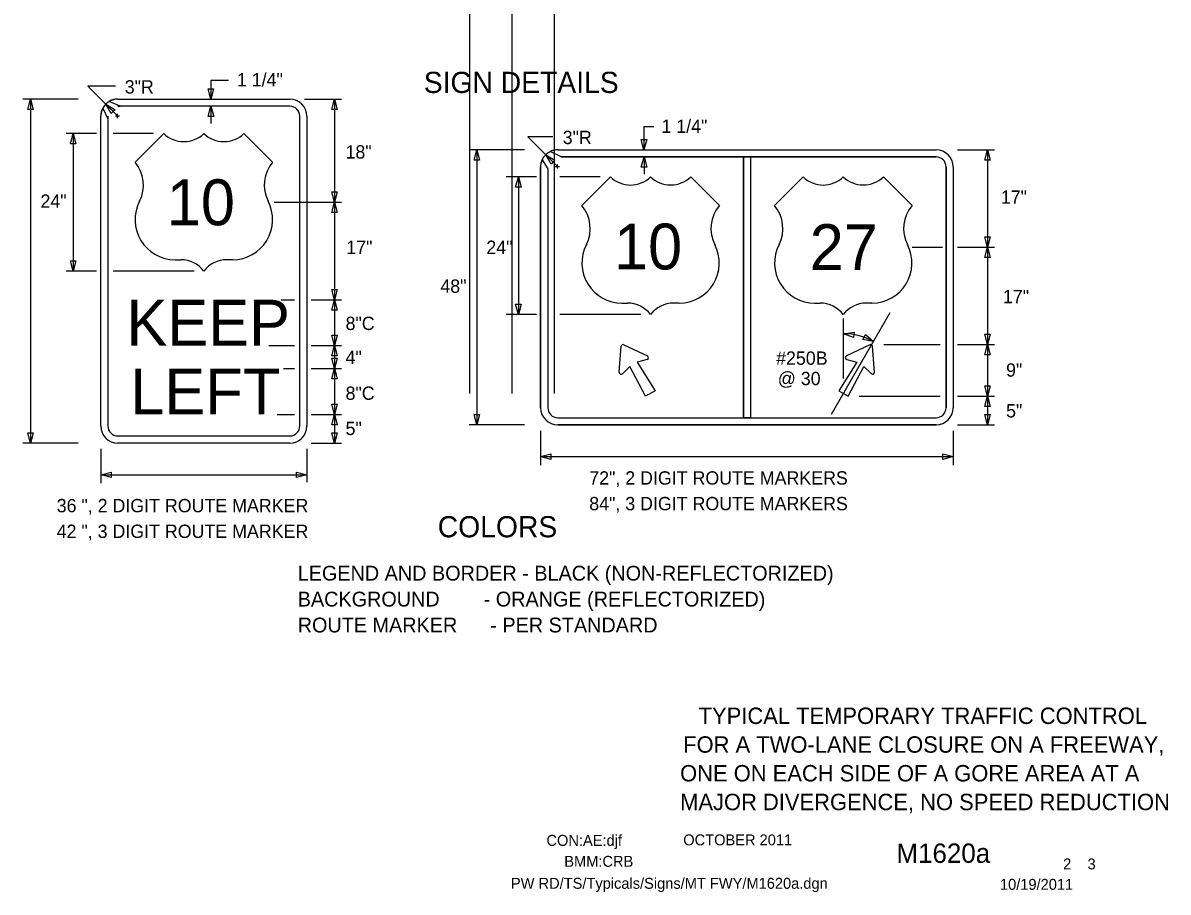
# Model space of a CAD drawing. Extents: x 16604 to 19504, y 6997 to 8305.
# Drawn here: x 17823 to 18472, y 7218 to 7711 of the extents above; entities that cross this region are included whole.
import ezdxf

# ---------------------------------------------------------------- set-up
doc = ezdxf.new("R2010")
doc.units = 0
for name, color, linetype in [('ALI_LEGAL_EX', 7, 'Continuous'), ('BORDER', 7, 'Continuous'), ('BORDER_SIGNAL_WO', 7, 'Continuous'), ('TRAFFIC_SIGNS_PR', 7, 'Continuous'), ('TYPICAL_EX', 7, 'Continuous'), ('TYPICAL_TEXT_DIMEN_PR', 7, 'Continuous')]:
    doc.layers.add(name, color=color, linetype=linetype)

msp = doc.modelspace()

# ---------------------------------------------------------------- linework, layer by layer
at = {"layer": 'ALI_LEGAL_EX'}
for p, q in [((18076.31, 7500.83), (18076.31, 8111.03)), ((18100.31, 7500.83), (18100.31, 8111.03)), ((18124.31, 7500.83), (18124.31, 8111.03))]:
    msp.add_line(p, q, dxfattribs=at)
at = {"layer": 'TRAFFIC_SIGNS_PR'}
for p, q in [((17877.83, 7663.57), (17871.73, 7666.31)), ((17876.63, 7667.63), (17974.13, 7667.63)), ((17869.05, 7664.01), (17868.04, 7662.5)), ((17868.07, 7662.43), (17870.94, 7656.39)), ((17974.13, 7663.57), (17876.63, 7663.57)), ((17866.88, 7482.38), (17866.88, 7657.88)), ((17870.94, 7657.88), (17870.94, 7482.38)), ((17979.81, 7482.38), (17979.81, 7657.88)), ((17983.88, 7657.88), (17983.88, 7482.38)), ((18126.15, 7638.93), (18340.65, 7638.93)), ((18126.15, 7638.93), (18340.65, 7638.93)), ((18117.32, 7633.19), (18120.46, 7628.15)), ((18128.1, 7634.88), (18121.87, 7637.9)), ((18128.09, 7634.87), (18231.37, 7634.87)), ((18340.65, 7634.87), (18128.09, 7634.87)), ((18231.37, 7634.87), (18231.37, 7486.99)), ((18235.43, 7634.87), (18235.43, 7486.99)), ((18235.43, 7634.87), (18340.65, 7634.87)), ((18116.4, 7629.18), (18116.4, 7492.68)), ((18116.4, 7492.68), (18116.4, 7629.18)), ((18120.46, 7628.13), (18120.46, 7492.68)), ((18120.46, 7628.13), (18120.46, 7492.68)), ((18346.33, 7629.18), (18346.33, 7583.43)), ((18346.34, 7492.68), (18346.34, 7629.18)), ((18350.4, 7629.18), (18350.4, 7492.68)), ((18350.4, 7629.18), (18350.4, 7492.68)), ((18346.33, 7583.43), (18346.33, 7492.68)), ((18163.66, 7528.38), (18176.98, 7522.02)), ((18303.13, 7528.38), (18289.82, 7522.02)), ((18161, 7512.79), (18162.15, 7527.5)), ((18305.8, 7512.79), (18304.65, 7527.5)), ((18126.15, 7486.99), (18340.65, 7486.99)), ((18126.15, 7482.93), (18340.65, 7482.93)), ((18340.65, 7482.93), (18126.15, 7482.93)), ((17876.63, 7476.69), (17974.13, 7476.69)), ((17974.13, 7472.63), (17876.63, 7472.63))]:
    msp.add_line(p, q, dxfattribs=at)
for points in [[(18128.09, 7634.87), (18128.07, 7634.87)], [(18120.46, 7628.15), (18120.46, 7628.13)], [(18176.81, 7520.05), (18171.09, 7518.47), (18181.31, 7502.3), (18175.91, 7499.18), (18167.02, 7516.12), (18162.79, 7511.95)], [(18289.98, 7520.05), (18295.7, 7518.47), (18285.49, 7502.3), (18290.88, 7499.18), (18299.78, 7516.12), (18304, 7511.95)]]:
    msp.add_lwpolyline(points, dxfattribs=at)
msp.add_lwpolyline([(18231.37, 7634.87), (18235.43, 7634.87), (18235.43, 7486.99), (18231.37, 7486.99)], close=True, dxfattribs=at)
for centre, radius, start, end in [((17876.63, 7657.88), 9.75, 90, 180), ((17876.04, 7660.05), 7.6, 85.58319, 124.53531), ((17974.13, 7657.88), 9.75, 0, 90), ((17873.91, 7658.47), 7.06, 145.86811, 184.82317), ((17877.23, 7667.99), 4.47, 262.2432, 277.7568), ((17974.13, 7657.88), 5.69, 0, 90), ((17865.48, 7657.13), 5.51, 352.24294, 7.75653), ((18126.15, 7629.18), 9.75, 90, 180), ((18126.15, 7629.18), 9.75, 90, 180), ((18125.47, 7632.36), 6.6, 84.11162, 123.06374), ((18340.65, 7629.18), 9.75, 0, 90), ((18340.65, 7629.18), 9.75, 0, 90), ((18122.53, 7629.89), 6.17, 147.60925, 186.56283), ((18127.09, 7642.05), 7.24, 277.81035, 278.05403), ((18340.65, 7629.18), 5.69, 0, 89.99421), ((18340.65, 7629.18), 5.69, 0, 90), ((18163.21, 7527.42), 1.06, 64.48226, 175.51774), ((18303.59, 7527.42), 1.06, 4.48226, 115.51774), ((18176.52, 7521.06), 1.06, 285.9885, 64.48226), ((18290.27, 7521.06), 1.06, 115.51774, 254.0115), ((18162.06, 7512.71), 1.06, 175.51775, 314.01151), ((18304.74, 7512.71), 1.06, 225.98849, 4.48225), ((18126.15, 7492.68), 9.75, 180, 270), ((18126.15, 7492.68), 9.75, 180, 270), ((18126.15, 7492.68), 5.69, 180, 270), ((18126.15, 7492.68), 5.69, 180, 270), ((18340.65, 7492.68), 9.75, 270, 0), ((18340.65, 7492.68), 5.69, 270, 0), ((18340.65, 7492.68), 9.75, 270, 0), ((18340.65, 7492.68), 5.69, 270, 0), ((17876.63, 7482.38), 9.75, 180, 270), ((17876.63, 7482.38), 5.69, 180, 270), ((17974.13, 7482.38), 5.69, 270, 0), ((17974.13, 7482.38), 9.75, 270, 0)]:
    msp.add_arc(centre, radius, start, end, dxfattribs=at)
at = {"layer": 'TYPICAL_EX'}
for p, q in [((17886.38, 7631.88), (17902.63, 7648.13)), ((17964.38, 7631.88), (17948.13, 7648.13)), ((18139.76, 7607.27), (18156.01, 7623.52)), ((18217.76, 7607.27), (18201.51, 7623.52)), ((18249.04, 7607.27), (18265.29, 7623.52)), ((18327.04, 7607.27), (18310.79, 7623.52)), ((17909.1, 7576.59), (17912.35, 7576.59)), ((17941.65, 7576.59), (17938.4, 7576.59)), ((18162.49, 7551.98), (18165.74, 7551.98)), ((18195.03, 7551.98), (18191.78, 7551.98)), ((18271.76, 7551.98), (18275.01, 7551.98)), ((18304.31, 7551.98), (18301.06, 7551.98))]:
    msp.add_line(p, q, dxfattribs=at)
for centre, radius, start, end in [((17914, 7659.96), 16.42, 226.14041, 313.85958), ((17936.75, 7659.97), 16.42, 226.14042, 313.85959), ((17870.98, 7618.87), 20.16, 333.09768, 40.19361), ((17979.78, 7618.87), 20.16, 139.80639, 206.90233), ((18167.39, 7635.35), 16.42, 226.14041, 313.85958), ((18190.13, 7635.36), 16.42, 226.14042, 313.85959), ((18276.66, 7635.35), 16.42, 226.14041, 313.85958), ((18299.41, 7635.36), 16.42, 226.14042, 313.85959), ((17909.14, 7599.31), 22.73, 152.6698, 269.90132), ((17941.61, 7599.31), 22.73, 270.09868, 27.3302), ((18124.36, 7594.26), 20.16, 333.09768, 40.19361), ((18233.16, 7594.26), 20.16, 139.80639, 206.90233), ((18233.64, 7594.26), 20.16, 333.09768, 40.19361), ((18342.44, 7594.26), 20.16, 139.80639, 206.90233), ((18162.53, 7574.7), 22.73, 152.6698, 269.90132), ((18194.99, 7574.7), 22.73, 270.09868, 27.3302), ((18271.81, 7574.7), 22.73, 152.6698, 269.90132), ((18304.27, 7574.7), 22.73, 270.09868, 27.3302), ((17912.39, 7560.31), 16.28, 37.1038, 90.13853), ((17938.36, 7560.31), 16.28, 89.86147, 142.8962), ((18165.78, 7535.7), 16.28, 37.1038, 90.13853), ((18191.74, 7535.7), 16.28, 89.86147, 142.8962), ((18275.06, 7535.7), 16.28, 37.1038, 90.13853), ((18301.02, 7535.7), 16.28, 89.86147, 142.8962)]:
    msp.add_arc(centre, radius, start, end, dxfattribs=at)
at = {"layer": 'TYPICAL_TEXT_DIMEN_PR'}
for p, q in [((17929.35, 7678.39), (17929.35, 7667.63)), ((17929.35, 7678.39), (17939.45, 7678.39)), ((17875.25, 7674.91), (17859.59, 7674.91)), ((17859.59, 7674.91), (17869.83, 7664.68)), ((17929.35, 7667.63), (17927.78, 7673.49)), ((17927.78, 7673.49), (17929.35, 7673.49)), ((17929.35, 7673.49), (17930.92, 7673.49)), ((17930.92, 7673.49), (17929.35, 7667.63)), ((17854.05, 7667.63), (17822.75, 7667.63)), ((17825.52, 7661.77), (17827.09, 7667.63)), ((17827.09, 7667.63), (17827.09, 7472.63)), ((17827.09, 7667.63), (17828.66, 7661.77)), ((17869.83, 7664.68), (17876.39, 7658.12)), ((17872.86, 7659.42), (17869.83, 7664.68)), ((17869.83, 7664.68), (17875.08, 7661.64)), ((17982.42, 7667.63), (18003.38, 7667.63)), ((17997.91, 7661.77), (17999.48, 7667.63)), ((17999.48, 7667.63), (17999.48, 7609.13)), ((17999.48, 7667.63), (18001.05, 7661.77)), ((17827.09, 7661.77), (17825.52, 7661.77)), ((17828.66, 7661.77), (17827.09, 7661.77)), ((17873.97, 7660.53), (17872.86, 7659.42)), ((17875.08, 7661.64), (17873.97, 7660.53)), ((17875.18, 7658.12), (17877.6, 7658.12)), ((17876.39, 7656.91), (17876.39, 7659.33)), ((17927.83, 7657.7), (17929.4, 7663.57)), ((17929.4, 7663.57), (17929.4, 7653.82)), ((17929.4, 7663.57), (17930.97, 7657.7)), ((17999.48, 7661.77), (17997.91, 7661.77)), ((18001.05, 7661.77), (17999.48, 7661.77)), ((17929.4, 7657.7), (17927.83, 7657.7)), ((17930.97, 7657.7), (17929.4, 7657.7)), ((18175.01, 7652.08), (18175.01, 7638.93)), ((18175.01, 7652.08), (18180.53, 7652.08)), ((17864.5, 7648.13), (17847.38, 7648.13)), ((17849.7, 7642.27), (17851.27, 7648.13)), ((17851.27, 7648.13), (17851.27, 7570.13)), ((17851.27, 7648.13), (17852.84, 7642.27)), ((17896.74, 7648.13), (17873.87, 7648.13)), ((18123.29, 7646.21), (18109.11, 7646.21)), ((18109.11, 7646.21), (18119.26, 7636.07)), ((17851.27, 7642.27), (17849.7, 7642.27)), ((17852.84, 7642.27), (17851.27, 7642.27)), ((18107.17, 7638.93), (18075.87, 7638.93)), ((18078.64, 7633.07), (18080.21, 7638.93)), ((18080.21, 7638.93), (18080.21, 7482.93)), ((18080.21, 7638.93), (18081.78, 7633.07)), ((18175.01, 7638.93), (18173.44, 7644.79)), ((18173.44, 7644.79), (18175.01, 7644.79)), ((18175.01, 7644.79), (18176.58, 7644.79)), ((18176.58, 7644.79), (18175.01, 7638.93)), ((18352.77, 7638.93), (18373.73, 7638.93)), ((18368.26, 7633.07), (18369.83, 7638.93)), ((18369.83, 7638.93), (18369.83, 7583.68)), ((18369.83, 7638.93), (18371.4, 7633.07)), ((18080.21, 7633.07), (18078.64, 7633.07)), ((18081.78, 7633.07), (18080.21, 7633.07)), ((18119.26, 7636.07), (18125.91, 7629.42)), ((18122.3, 7630.81), (18119.26, 7636.07)), ((18119.26, 7636.07), (18124.52, 7633.03)), ((18124.52, 7633.03), (18123.41, 7631.92)), ((18173.48, 7629.01), (18175.06, 7634.87)), ((18173.48, 7629.01), (18175.06, 7634.87)), ((18175.05, 7634.87), (18175.05, 7625.12)), ((18175.06, 7634.87), (18176.63, 7629.01)), ((18175.06, 7634.87), (18176.63, 7629.01)), ((18369.83, 7633.07), (18368.26, 7633.07)), ((18371.4, 7633.07), (18369.83, 7633.07)), ((18123.41, 7631.92), (18122.3, 7630.81)), ((18124.7, 7629.42), (18127.12, 7629.42)), ((18125.91, 7628.21), (18125.91, 7630.63)), ((18175.06, 7629.01), (18173.48, 7629.01)), ((18175.06, 7629.01), (18173.48, 7629.01)), ((18176.63, 7629.01), (18175.06, 7629.01)), ((18176.63, 7629.01), (18175.06, 7629.01)), ((18114.03, 7623.52), (18096.9, 7623.52)), ((18102.19, 7617.66), (18103.77, 7623.52)), ((18103.77, 7623.52), (18103.77, 7545.52)), ((18103.77, 7623.52), (18105.34, 7617.66)), ((18150.13, 7623.52), (18127.25, 7623.52)), ((17999.48, 7609.13), (17997.91, 7614.99)), ((17997.91, 7614.99), (17999.48, 7614.99)), ((17999.48, 7614.99), (18001.05, 7614.99)), ((18001.05, 7614.99), (17999.48, 7609.13)), ((18103.77, 7617.66), (18102.19, 7617.66)), ((18105.34, 7617.66), (18103.77, 7617.66)), ((17965.27, 7609.13), (18003.38, 7609.13)), ((17997.91, 7603.27), (17999.48, 7609.13)), ((17999.48, 7609.13), (17999.48, 7553.88)), ((17999.48, 7609.13), (18001.05, 7603.27)), ((17999.48, 7603.27), (17997.91, 7603.27)), ((18001.05, 7603.27), (17999.48, 7603.27)), ((18369.83, 7583.68), (18368.26, 7589.54)), ((18368.26, 7589.54), (18369.83, 7589.54)), ((18369.83, 7589.54), (18371.4, 7589.54)), ((18371.4, 7589.54), (18369.83, 7583.68)), ((18327.21, 7583.68), (18344.36, 7583.68)), ((18352.77, 7583.68), (18373.73, 7583.68)), ((18368.26, 7577.82), (18369.83, 7583.68)), ((18369.83, 7583.68), (18369.83, 7528.43)), ((18369.83, 7583.68), (18371.4, 7577.82)), ((17851.27, 7570.13), (17849.7, 7575.99)), ((17849.7, 7575.99), (17851.27, 7575.99)), ((17851.27, 7575.99), (17852.84, 7575.99)), ((17852.84, 7575.99), (17851.27, 7570.13)), ((18369.83, 7577.82), (18368.26, 7577.82)), ((18371.4, 7577.82), (18369.83, 7577.82)), ((17864.5, 7570.13), (17847.38, 7570.13)), ((17919.87, 7570.13), (17873.87, 7570.13)), ((17999.48, 7553.88), (17997.91, 7559.74)), ((17997.91, 7559.74), (17999.48, 7559.74)), ((17999.48, 7559.74), (18001.05, 7559.74)), ((18001.05, 7559.74), (17999.48, 7553.88)), ((17969.21, 7553.88), (17976.89, 7553.88)), ((17986.25, 7553.88), (18003.38, 7553.88)), ((17997.91, 7548.02), (17999.48, 7553.88)), ((17999.48, 7548.02), (17997.91, 7548.02)), ((17999.48, 7553.88), (17999.48, 7527.88)), ((17999.48, 7553.88), (18001.05, 7548.02)), ((18001.05, 7548.02), (17999.48, 7548.02)), ((18103.77, 7545.52), (18102.19, 7551.38)), ((18102.19, 7551.38), (18103.77, 7551.38)), ((18103.77, 7551.38), (18105.34, 7551.38)), ((18105.34, 7551.38), (18103.77, 7545.52)), ((18114.03, 7545.52), (18096.9, 7545.52)), ((18173.25, 7545.52), (18127.25, 7545.52)), ((18281.43, 7489.03), (18314.67, 7546.62)), ((18288.19, 7509.18), (18288.19, 7543.18)), ((18288.22, 7534.62), (18294.21, 7535.58)), ((18293.89, 7532.46), (18288.22, 7534.62)), ((18294.21, 7535.58), (18294.05, 7534.02)), ((17999.48, 7527.88), (17997.91, 7533.74)), ((17997.91, 7533.74), (17999.48, 7533.74)), ((17999.48, 7533.74), (18001.05, 7533.74)), ((18001.05, 7533.74), (17999.48, 7527.88)), ((18294.05, 7534.02), (18293.89, 7532.46)), ((18299.2, 7531.3), (18299.89, 7532.71)), ((18305.17, 7530.17), (18299.2, 7531.3)), ((18299.89, 7532.71), (18300.57, 7534.13)), ((18300.57, 7534.13), (18305.17, 7530.17)), ((18311.14, 7528.43), (18343.01, 7528.43)), ((18352.77, 7528.43), (18373.73, 7528.43)), ((18369.83, 7528.43), (18368.26, 7534.29)), ((18368.26, 7534.29), (18369.83, 7534.29)), ((18368.26, 7522.57), (18369.83, 7528.43)), ((18369.83, 7534.29), (18371.4, 7534.29)), ((18371.4, 7534.29), (18369.83, 7528.43)), ((18369.83, 7528.43), (18369.83, 7499.18)), ((18369.83, 7528.43), (18371.4, 7522.57)), ((17962.19, 7527.88), (17976.89, 7527.88)), ((17986.25, 7527.88), (18003.38, 7527.88)), ((17997.91, 7522.02), (17999.48, 7527.88)), ((17999.48, 7522.02), (17997.91, 7522.02)), ((17999.48, 7527.88), (17999.48, 7514.88)), ((17999.48, 7527.88), (18001.05, 7522.02)), ((18001.05, 7522.02), (17999.48, 7522.02)), ((18369.83, 7522.57), (18368.26, 7522.57)), ((18371.4, 7522.57), (18369.83, 7522.57)), ((17999.48, 7514.88), (17997.91, 7520.74)), ((17997.91, 7520.74), (17999.48, 7520.74)), ((17999.48, 7520.74), (18001.05, 7520.74)), ((18001.05, 7520.74), (17999.48, 7514.88)), ((17970.54, 7514.88), (17976.89, 7514.88)), ((17986.25, 7514.88), (18003.38, 7514.88)), ((17997.91, 7509.02), (17999.48, 7514.88)), ((17999.48, 7509.02), (17997.91, 7509.02)), ((17999.48, 7514.88), (17999.48, 7488.88)), ((17999.48, 7514.88), (18001.05, 7509.02)), ((18001.05, 7509.02), (17999.48, 7509.02)), ((18369.83, 7499.18), (18368.26, 7505.04)), ((18368.26, 7505.04), (18369.83, 7505.04)), ((18369.83, 7505.04), (18371.4, 7505.04)), ((18371.4, 7505.04), (18369.83, 7499.18)), ((18297, 7499.18), (18343.01, 7499.18)), ((18352.77, 7499.18), (18373.73, 7499.18)), ((18368.26, 7493.32), (18369.83, 7499.18)), ((18369.83, 7499.18), (18369.83, 7482.93)), ((18369.83, 7499.18), (18371.4, 7493.32)), ((17999.48, 7488.88), (17997.91, 7494.74)), ((17997.91, 7494.74), (17999.48, 7494.74)), ((17999.48, 7494.74), (18001.05, 7494.74)), ((18001.05, 7494.74), (17999.48, 7488.88)), ((18369.83, 7493.32), (18368.26, 7493.32)), ((18371.4, 7493.32), (18369.83, 7493.32)), ((17967.04, 7488.88), (17976.89, 7488.88)), ((17986.25, 7488.88), (18003.38, 7488.88)), ((17997.91, 7483.02), (17999.48, 7488.88)), ((17999.48, 7483.02), (17997.91, 7483.02)), ((17999.48, 7488.88), (17999.48, 7472.63)), ((17999.48, 7488.88), (18001.05, 7483.02)), ((18001.05, 7483.02), (17999.48, 7483.02)), ((18107.17, 7482.93), (18075.87, 7482.93)), ((18080.21, 7482.93), (18078.64, 7488.79)), ((18078.64, 7488.79), (18080.21, 7488.79)), ((18080.21, 7488.79), (18081.78, 7488.79)), ((18081.78, 7488.79), (18080.21, 7482.93)), ((18352.77, 7482.93), (18369.9, 7482.93)), ((18352.77, 7482.93), (18373.73, 7482.93)), ((18352.77, 7482.93), (18369.9, 7482.93)), ((18369.83, 7482.93), (18368.26, 7488.79)), ((18368.26, 7488.79), (18369.83, 7488.79)), ((18369.83, 7488.79), (18371.4, 7488.79)), ((18371.4, 7488.79), (18369.83, 7482.93)), ((17827.09, 7472.63), (17825.52, 7478.49)), ((17825.52, 7478.49), (17827.09, 7478.49)), ((17827.09, 7478.49), (17828.66, 7478.49)), ((17828.66, 7478.49), (17827.09, 7472.63)), ((17999.48, 7472.63), (17997.91, 7478.49)), ((17997.91, 7478.49), (17999.48, 7478.49)), ((17999.48, 7478.49), (18001.05, 7478.49)), ((18001.05, 7478.49), (17999.48, 7472.63)), ((18116.4, 7479.59), (18116.4, 7460.02)), ((18350.4, 7479.59), (18350.4, 7460.02)), ((17854.05, 7472.63), (17822.75, 7472.63)), ((17986.25, 7472.63), (18003.38, 7472.63)), ((17866.88, 7469.28), (17866.88, 7449.93)), ((17983.88, 7469.28), (17983.88, 7450.39)), ((18116.4, 7464.96), (18122.26, 7466.53)), ((18116.4, 7464.96), (18350.4, 7464.96)), ((18122.26, 7463.39), (18116.4, 7464.96)), ((18122.26, 7466.53), (18122.26, 7464.96)), ((18122.26, 7464.96), (18122.26, 7463.39)), ((18344.54, 7464.96), (18344.54, 7466.53)), ((18344.54, 7466.53), (18350.4, 7464.96)), ((18350.4, 7464.96), (18344.54, 7463.39)), ((18344.54, 7463.39), (18344.54, 7464.96)), ((17866.88, 7454.66), (17872.74, 7456.23)), ((17866.88, 7454.66), (17983.88, 7454.66)), ((17872.74, 7453.09), (17866.88, 7454.66)), ((17872.74, 7456.23), (17872.74, 7454.66)), ((17872.74, 7454.66), (17872.74, 7453.09)), ((17978.01, 7454.66), (17978.01, 7456.23)), ((17978.01, 7456.23), (17983.88, 7454.66)), ((17983.88, 7454.66), (17978.01, 7453.09)), ((17978.01, 7453.09), (17978.01, 7454.66))]:
    msp.add_line(p, q, dxfattribs=at)
msp.add_arc((18288.38, 7500.18), 34.39, 60.74521, 90.32117, dxfattribs=at)

# ---------------------------------------------------------------- texts
at = {"layer": 'BORDER'}
for s, p in [('TYPICAL TEMPORARY TRAFFIC CONTROL', (18206.02, 7313.39)), ('FOR A TWO-LANE CLOSURE ON A FREEWAY,', (18197.26, 7297.1)), ('ONE ON EACH SIDE OF A GORE AREA AT A', (18195.5, 7280.81)), ('MAJOR DIVERGENCE, NO SPEED REDUCTION', (18195.52, 7264.52))]:
    msp.add_text(s, height=9.3, dxfattribs=at).set_placement(p)
at = {"layer": 'BORDER_SIGNAL_WO'}
for s, height, p in [('CON:AE:djf  ', 6.2, (18119.69, 7244.31)), ('    OCTOBER 2011    ', 6.2, (18188.08, 7244.59)), ('    M1620a   ', 11, (18301.86, 7234.63)), ('BMM:CRB   ', 6.2, (18129.81, 7232.42)), (' 2    3 ', 6.2, (18410.45, 7230.95)), ('PW RD/TS/Typicals/Signs/MT FWY/M1620a.dgn      ', 6.2, (18099.55, 7219.96)), ('10/19/2011', 6.2, (18376.93, 7219.38))]:
    msp.add_text(s, height=height, dxfattribs=at).set_placement(p)
at = {"layer": 'TRAFFIC_SIGNS_PR'}
for s, p in [('10', (17904.35, 7596.13)), ('10', (18158, 7571.06)), ('27', (18269.01, 7570.7)), ('KEEP', (17881.48, 7527.88)), ('LEFT', (17883.71, 7488.88))]:
    msp.add_text(s, height=26, dxfattribs=at).set_placement(p)
at = {"layer": 'TYPICAL_TEXT_DIMEN_PR'}
for s, height, p in [('3"R', 7.55, (17880.52, 7670.79)), ('1 1/4"', 7.55, (17944.15, 7674.88)), ('SIGN DETAILS', 12, (18050.1, 7671.1)), ('1 1/4"', 7.55, (18184.93, 7648.5)), ('3"R', 7.55, (18128.93, 7642.13)), ('18"', 7.55, (18005.72, 7633.9)), ('24"', 7.55, (17832.72, 7606.01)), ('17"', 7.55, (18377.41, 7608.29)), ('17"', 7.55, (18006.18, 7579.85)), ('24"', 7.55, (18085.62, 7579.85)), ('48"', 7.55, (18059.51, 7557.83)), ('17"', 7.55, (18378.61, 7551.93)), ('8"C', 7.55, (18005.75, 7536.73)), ('4" ', 7.55, (18005.75, 7517.48)), ('#250B', 7.55, (18249.96, 7517.02)), ('9"', 7.55, (18380.39, 7510.27)), ('@ 30', 7.55, (18250.9, 7505.47)), ('8"C', 7.55, (18005.75, 7497.15)), ('5"', 7.55, (18380.39, 7487.17)), ('5" ', 7.55, (18005.75, 7477.17)), ('72", 2 DIGIT ROUTE MARKERS', 7.55, (18143.98, 7449.09)), ('36 ", 2 DIGIT ROUTE MARKER', 7.55, (17841.92, 7433.4)), ('84", 3 DIGIT ROUTE MARKERS', 7.55, (18143.98, 7434.55)), ('COLORS', 12, (18058.04, 7419.21)), ('42 ", 3 DIGIT ROUTE MARKER', 7.55, (17841.92, 7418.85)), ('LEGEND AND BORDER - BLACK (NON-REFLECTORIZED)', 8.4, (17978.62, 7394.68)), ('BACKGROUND        - ORANGE (REFLECTORIZED)', 8.4, (17978.62, 7379.98)), ('ROUTE MARKER      - PER STANDARD', 8.4, (17978.62, 7365.28))]:
    msp.add_text(s, height=height, dxfattribs=at).set_placement(p)

doc.saveas('drawing.dxf')
